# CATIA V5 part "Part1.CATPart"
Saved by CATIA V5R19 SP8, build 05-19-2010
Part number: Recipient
Bounding box of the stored display mesh (mm): x 0 to 160, y -130 to 130, z -129.809 to 129.809
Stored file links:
  G:\EU_thinkMotion\CFAO_2010\SIL_groupe2\SIL_groupe2\msauret\Brevet_Sauret_parametre\Part1.CATPart
  F:\Brevet_Sauret paramétré\Product3.CATProduct
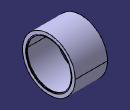
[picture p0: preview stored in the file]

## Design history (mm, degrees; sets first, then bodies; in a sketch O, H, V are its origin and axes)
Set1
  Plane1 to Plane6: linked copy from another document
Body1 (main body)
  Sketch1 on Plane1, origin (0, 0, 0), H (0, 1, 0), V (0, 0, 1)
    circle A1 centre (0, 0) radius 130
    radius A1 = 130
  Pad1: profile Sketch1, direction (1, 0, 0), up to Plane3
  Sketch2 on Plane2, origin (-4, 0, 0), H (0, 1, 0), V (0, 0, 1)
    circle A1 centre (0, 0) radius 125
  Pocket1: profile Sketch2, direction (-1, 0, 0), up to Plane5
  Sketch3 on Plane3, origin (160, 0, 0), H (0, 1, 0), V (0, 0, 1)
    circle A1 centre (0, 0) radius 110
  Pocket2: profile Sketch3, direction (-1, 0, 0), up to Plane5
  Sketch4 on Plane3, origin (160, 0, 0), H (0, 1, 0), V (0, 0, 1)
    circle A1 centre (0, 0) radius 114
  Pocket3: profile Sketch4, direction (-1, 0, 0), up to Plane6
